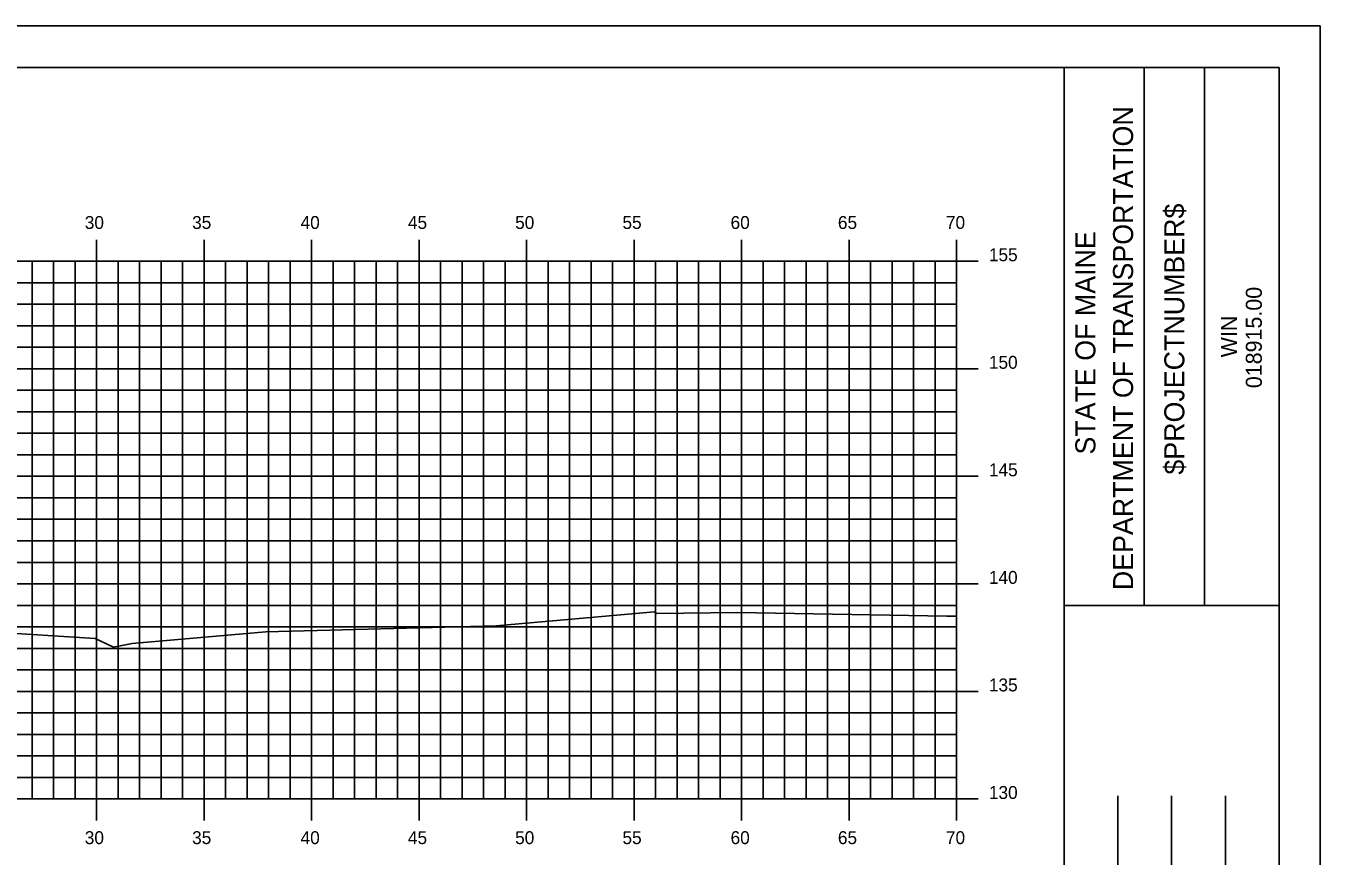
# Model space of a CAD drawing. Extents: x 851639 to 851810, y 365876 to 365986.
# Drawn here: x 851748.4 to 851808.6, y 365947.2 to 365985.8 of the extents above; entities that cross this region are included whole.
import ezdxf

# ---------------------------------------------------------------- set-up
doc = ezdxf.new("R2010")
doc.units = 0
for name, color, linetype in [('BORDER', 7, 'Continuous'), ('H_V ANNOTATION', 7, 'Continuous'), ('MAJOR', 7, 'Continuous'), ('MINOR', 7, 'Continuous'), ('PLOT BOUNDARY', 7, 'Continuous'), ('S_Roadway_Centerline', 7, 'Continuous')]:
    doc.layers.add(name, color=color, linetype=linetype)

msp = doc.modelspace()

# ---------------------------------------------------------------- linework, layer by layer
at = {"layer": 'BORDER'}
for p, q in [((851796.655, 365878.833), (851796.655, 365983.833)), ((851800.384, 365958.83), (851800.384, 365983.83)), ((851803.179, 365958.83), (851803.179, 365983.83)), ((851796.656, 365958.827), (851806.655, 365958.827)), ((851799.155, 365941.336), (851799.155, 365949.984)), ((851801.655, 365941.336), (851801.655, 365949.984)), ((851804.155, 365941.336), (851804.155, 365949.984))]:
    msp.add_line(p, q, dxfattribs=at)
msp.add_lwpolyline([(851646.655, 365878.833), (851806.655, 365878.833), (851806.655, 365983.833), (851646.655, 365983.833)], close=True, dxfattribs=at)
at = {"layer": 'MAJOR'}
for p, q in [((851751.655, 365975.835), (851751.655, 365974.833)), ((851756.655, 365975.835), (851756.655, 365974.833)), ((851761.655, 365975.835), (851761.655, 365974.833)), ((851766.655, 365975.835), (851766.655, 365974.833)), ((851771.655, 365975.835), (851771.655, 365974.833)), ((851776.655, 365975.835), (851776.655, 365974.833)), ((851781.655, 365975.835), (851781.655, 365974.833)), ((851786.655, 365975.835), (851786.655, 365974.833)), ((851791.655, 365975.835), (851791.655, 365974.833)), ((851651.655, 365974.833), (851791.655, 365974.833)), ((851651.655, 365974.833), (851791.655, 365974.833)), ((851751.655, 365949.833), (851751.655, 365974.833)), ((851756.655, 365949.833), (851756.655, 365974.833)), ((851761.655, 365949.833), (851761.655, 365974.833)), ((851766.655, 365949.833), (851766.655, 365974.833)), ((851771.655, 365949.833), (851771.655, 365974.833)), ((851776.655, 365949.833), (851776.655, 365974.833)), ((851781.655, 365949.833), (851781.655, 365974.833)), ((851786.655, 365949.833), (851786.655, 365974.833)), ((851792.657, 365974.833), (851790.653, 365974.833)), ((851791.655, 365949.833), (851791.655, 365974.833)), ((851791.655, 365949.833), (851791.655, 365974.833)), ((851651.655, 365969.833), (851791.655, 365969.833)), ((851792.657, 365969.833), (851790.653, 365969.833)), ((851651.655, 365964.833), (851791.655, 365964.833)), ((851792.657, 365964.833), (851790.653, 365964.833)), ((851651.655, 365959.833), (851791.655, 365959.833)), ((851792.657, 365959.833), (851790.653, 365959.833)), ((851651.655, 365954.833), (851791.655, 365954.833)), ((851792.657, 365954.833), (851790.653, 365954.833)), ((851651.655, 365949.833), (851791.655, 365949.833)), ((851651.655, 365949.833), (851791.655, 365949.833)), ((851751.655, 365948.831), (851751.655, 365949.833)), ((851756.655, 365948.831), (851756.655, 365949.833)), ((851761.655, 365948.831), (851761.655, 365949.833)), ((851766.655, 365948.831), (851766.655, 365949.833)), ((851771.655, 365948.831), (851771.655, 365949.833)), ((851776.655, 365948.831), (851776.655, 365949.833)), ((851781.655, 365948.831), (851781.655, 365949.833)), ((851786.655, 365948.831), (851786.655, 365949.833)), ((851792.657, 365949.833), (851790.653, 365949.833)), ((851791.655, 365948.831), (851791.655, 365949.833))]:
    msp.add_line(p, q, dxfattribs=at)
at = {"layer": 'MINOR'}
for p, q in [((851748.655, 365949.833), (851748.655, 365974.833)), ((851749.655, 365949.833), (851749.655, 365974.833)), ((851750.655, 365949.833), (851750.655, 365974.833)), ((851752.655, 365949.833), (851752.655, 365974.833)), ((851753.655, 365949.833), (851753.655, 365974.833)), ((851754.655, 365949.833), (851754.655, 365974.833)), ((851755.655, 365949.833), (851755.655, 365974.833)), ((851757.655, 365949.833), (851757.655, 365974.833)), ((851758.655, 365949.833), (851758.655, 365974.833)), ((851759.655, 365949.833), (851759.655, 365974.833)), ((851760.655, 365949.833), (851760.655, 365974.833)), ((851762.655, 365949.833), (851762.655, 365974.833)), ((851763.655, 365949.833), (851763.655, 365974.833)), ((851764.655, 365949.833), (851764.655, 365974.833)), ((851765.655, 365949.833), (851765.655, 365974.833)), ((851767.655, 365949.833), (851767.655, 365974.833)), ((851768.655, 365949.833), (851768.655, 365974.833)), ((851769.655, 365949.833), (851769.655, 365974.833)), ((851770.655, 365949.833), (851770.655, 365974.833)), ((851772.655, 365949.833), (851772.655, 365974.833)), ((851773.655, 365949.833), (851773.655, 365974.833)), ((851774.655, 365949.833), (851774.655, 365974.833)), ((851775.655, 365949.833), (851775.655, 365974.833)), ((851777.655, 365949.833), (851777.655, 365974.833)), ((851778.655, 365949.833), (851778.655, 365974.833)), ((851779.655, 365949.833), (851779.655, 365974.833)), ((851780.655, 365949.833), (851780.655, 365974.833)), ((851782.655, 365949.833), (851782.655, 365974.833)), ((851783.655, 365949.833), (851783.655, 365974.833)), ((851784.655, 365949.833), (851784.655, 365974.833)), ((851785.655, 365949.833), (851785.655, 365974.833)), ((851787.655, 365949.833), (851787.655, 365974.833)), ((851788.655, 365949.833), (851788.655, 365974.833)), ((851789.655, 365949.833), (851789.655, 365974.833)), ((851790.655, 365949.833), (851790.655, 365974.833)), ((851651.655, 365973.833), (851791.655, 365973.833)), ((851791.655, 365973.833), (851790.653, 365973.833)), ((851651.655, 365972.833), (851791.655, 365972.833)), ((851791.655, 365972.833), (851790.653, 365972.833)), ((851651.655, 365971.833), (851791.655, 365971.833)), ((851791.655, 365971.833), (851790.653, 365971.833)), ((851651.655, 365970.833), (851791.655, 365970.833)), ((851791.655, 365970.833), (851790.653, 365970.833)), ((851651.655, 365968.833), (851791.655, 365968.833)), ((851791.655, 365968.833), (851790.653, 365968.833)), ((851651.655, 365967.833), (851791.655, 365967.833)), ((851791.655, 365967.833), (851790.653, 365967.833)), ((851651.655, 365966.833), (851791.655, 365966.833)), ((851791.655, 365966.833), (851790.653, 365966.833)), ((851651.655, 365965.833), (851791.655, 365965.833)), ((851791.655, 365965.833), (851790.653, 365965.833)), ((851651.655, 365963.833), (851791.655, 365963.833)), ((851791.655, 365963.833), (851790.653, 365963.833)), ((851651.655, 365962.833), (851791.655, 365962.833)), ((851791.655, 365962.833), (851790.653, 365962.833)), ((851651.655, 365961.833), (851791.655, 365961.833)), ((851791.655, 365961.833), (851790.653, 365961.833)), ((851651.655, 365960.833), (851791.655, 365960.833)), ((851791.655, 365960.833), (851790.653, 365960.833)), ((851651.655, 365958.833), (851791.655, 365958.833)), ((851791.655, 365958.833), (851790.653, 365958.833)), ((851651.655, 365957.833), (851791.655, 365957.833)), ((851791.655, 365957.833), (851790.653, 365957.833)), ((851651.655, 365956.833), (851791.655, 365956.833)), ((851791.655, 365956.833), (851790.653, 365956.833)), ((851651.655, 365955.833), (851791.655, 365955.833)), ((851791.655, 365955.833), (851790.653, 365955.833)), ((851651.655, 365953.833), (851791.655, 365953.833)), ((851791.655, 365953.833), (851790.653, 365953.833)), ((851651.655, 365952.833), (851791.655, 365952.833)), ((851791.655, 365952.833), (851790.653, 365952.833)), ((851651.655, 365951.833), (851791.655, 365951.833)), ((851791.655, 365951.833), (851790.653, 365951.833)), ((851651.655, 365950.833), (851791.655, 365950.833)), ((851791.655, 365950.833), (851790.653, 365950.833))]:
    msp.add_line(p, q, dxfattribs=at)
at = {"layer": 'PLOT BOUNDARY'}
msp.add_lwpolyline([(851638.562, 365875.774), (851808.562, 365875.774), (851808.562, 365985.774), (851638.562, 365985.774)], close=True, dxfattribs=at)
at = {"layer": 'S_Roadway_Centerline'}
msp.add_lwpolyline([(851746.683, 365957.602), (851751.58, 365957.287), (851752.445, 365956.882), (851753.31, 365957.058), (851759.518, 365957.598), (851770.244, 365957.879), (851777.599, 365958.538), (851777.715, 365958.458), (851781.47, 365958.503), (851791.202, 365958.325), (851791.655, 365958.337)], dxfattribs=at)

# ---------------------------------------------------------------- texts
at = {"layer": 'BORDER'}
for s, height, p in [('DEPARTMENT OF TRANSPORTATION', 0.93176, (851799.862, 365959.539)), ('$PROJECTNUMBER$', 0.93176, (851802.247, 365964.912)), ('STATE OF MAINE', 0.93176, (851798.11, 365965.845)), ('018915.00', 0.7453, (851805.851, 365968.931)), ('WIN', 0.7453, (851804.692, 365970.363))]:
    msp.add_text(s, height=height, rotation=90, dxfattribs=at).set_placement(p)
at = {"layer": 'H_V ANNOTATION'}
for s, p in [('30', (851751.104, 365976.333)), ('35', (851756.096, 365976.333)), ('40', (851761.141, 365976.333)), ('45', (851766.133, 365976.333)), ('50', (851771.12, 365976.333)), ('55', (851776.112, 365976.333)), ('60', (851781.141, 365976.333)), ('65', (851786.133, 365976.333)), ('70', (851791.157, 365976.333)), ('155', (851793.155, 365974.833)), ('150', (851793.155, 365969.833)), ('145', (851793.155, 365964.833)), ('140', (851793.155, 365959.833)), ('135', (851793.155, 365954.833)), ('130', (851793.155, 365949.833)), ('30', (851751.104, 365947.733)), ('35', (851756.096, 365947.733)), ('40', (851761.141, 365947.733)), ('45', (851766.133, 365947.733)), ('50', (851771.12, 365947.733)), ('55', (851776.112, 365947.733)), ('60', (851781.141, 365947.733)), ('65', (851786.133, 365947.733)), ('70', (851791.157, 365947.733))]:
    msp.add_text(s, height=0.6, dxfattribs=at).set_placement(p)

doc.saveas('drawing.dxf')
